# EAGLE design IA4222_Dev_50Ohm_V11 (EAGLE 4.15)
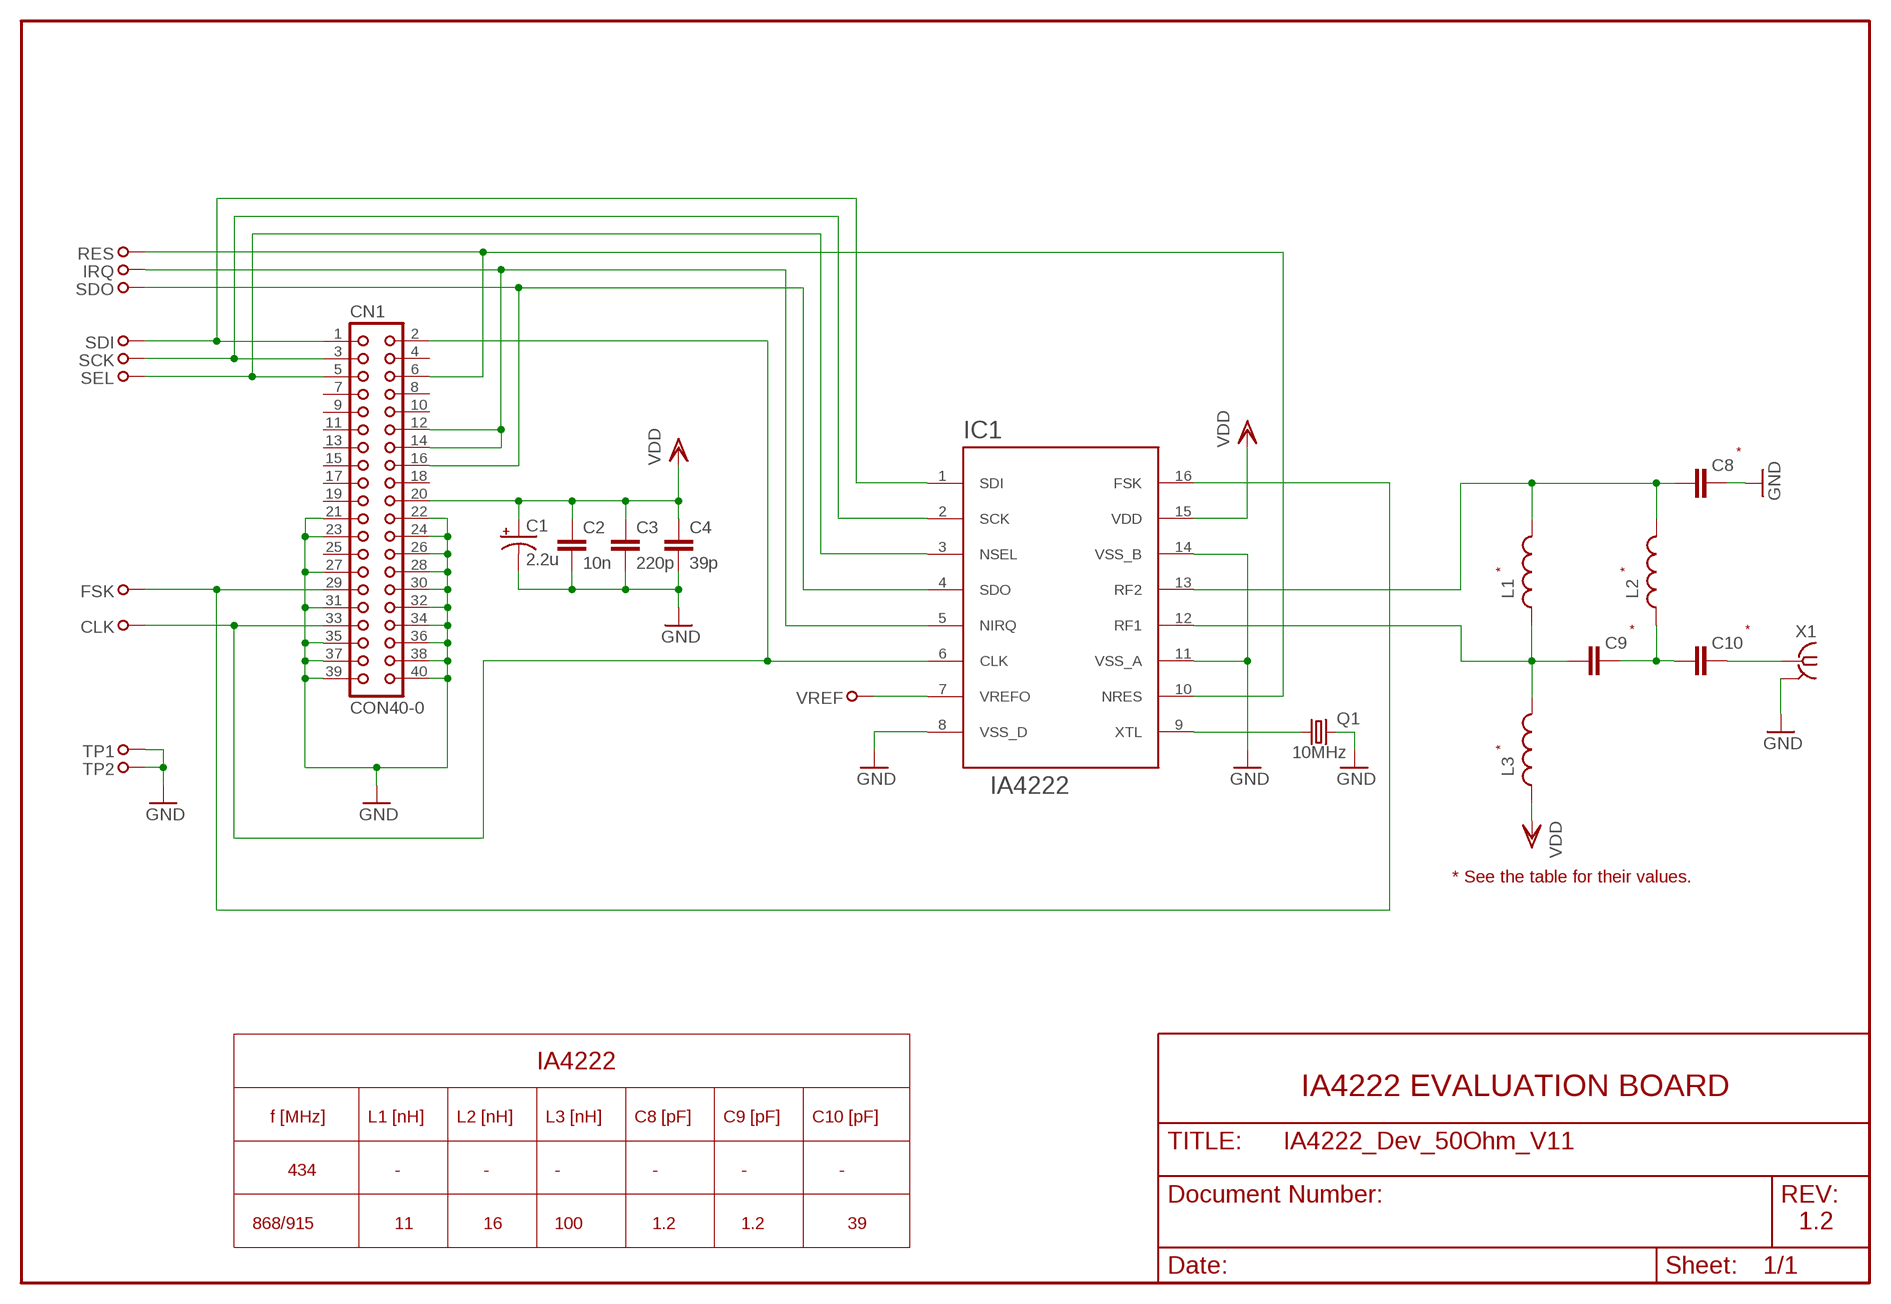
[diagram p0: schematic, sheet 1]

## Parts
C1  2.2u  CPOL-USA/3216-18R  [A/3216-18R]
C2  10n  C-EUC0603K  [C0603K]
C3  220p  C-EUC0603K  [C0603K]
C4  39p  C-EUC0603K  [C0603K]
C8  C-EUC0603K  [C0603K]
C9  C-EUC0603K  [C0603K]
C10  C-EUC0603K  [C0603K]
CLK  TESTPOINT39MIL  [TESTPOINT1,0]
CN1  CON40-0  [PANDUIT-057-040-0-INTEGRATION]
FSK  TESTPOINT39MIL  [TESTPOINT1,0]
IC1  IA4222  TESSIE  [TSSOP-16(NEW)]
IRQ  TESTPOINT39MIL  [TESTPOINT1,0]
L1  INDUCTCOILCRAFT-0603  [L1608]
L2  INDUCTCOILCRAFT-0603  [L1608]
L3  INDUCTCOILCRAFT-0603  [L1608]
Q1  10MHz  CRYTALSM49  [SM49]
RES  TESTPOINT39MIL  [TESTPOINT1,0]
SCK  TESTPOINT39MIL  [TESTPOINT1,0]
SDI  TESTPOINT39MIL  [TESTPOINT1,0]
SDO  TESTPOINT39MIL  [TESTPOINT1,0]
SEL  TESTPOINT39MIL  [TESTPOINT1,0]
TP1  TESTPOINT39MIL  [TESTPOINT1,0]
TP2  TESTPOINT39MIL  [TESTPOINT1,0]
VREF  TESTPOINT39MIL  [TESTPOINT1,0]
X1  BU-SMA-H  [BU-SMA-H]

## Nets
GND: C1.- C2.2 C3.2 C4.2 C8.2 CN1.21 CN1.22 CN1.23 CN1.24 CN1.26 CN1.27 CN1.28 CN1.30 CN1.31 CN1.32 CN1.34 CN1.35 CN1.36 CN1.37 CN1.38 CN1.39 CN1.40 IC1.8(VSS_D) IC1.11(VSS_A) IC1.14(VSS_B) Q1.2 TP1.1 TP2.1 X1.2(GND)
N$1: CN1.3 IC1.2(SCK) SCK.1
N$2: C8.1 IC1.13(RF2) L1.2 L2.2
N$3: CN1.5 IC1.3(NSEL) SEL.1
N$4: CLK.1 CN1.2 CN1.33 IC1.6(CLK)
N$5: IC1.7(VREFO) VREF.1
N$7: C9.1 IC1.12(RF1) L1.1 L3.2
N$8: IC1.9(XTL) Q1.1
N$9: CN1.12 CN1.14 IC1.5(NIRQ) IRQ.1
N$10: CN1.6 IC1.10(NRES) RES.1
N$11: C9.2 C10.1 L2.1
N$13: C10.2 X1.1
N$14: CN1.1 IC1.1(SDI) SDI.1
N$19: CN1.29 FSK.1 IC1.16(FSK)
TINA: CN1.16 IC1.4(SDO) SDO.1
VDD: C1.+ C2.1 C3.1 C4.1 CN1.20 IC1.15(VDD) L3.1
Unconnected: CN1.4 CN1.7 CN1.8 CN1.9 CN1.10 CN1.11 CN1.13 CN1.15 CN1.17 CN1.18 CN1.19 CN1.25

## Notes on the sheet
- *
- * | *
- * | *
- *
- * See the table for their values.
- IA4222
- IA4222 EVALUATION BOARD
- f [MHz] | L1 [nH] | L2 [nH] | L3 [nH] | C8 [pF] | C9 [pF] | C10 [pF]
- 434 | - | - | - | - | - | -
- 868/915 | 11 | 16 | 100 | 1.2 | 1.2 | 39 | 1.2

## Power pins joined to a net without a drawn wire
GND: X1.3(GND) X1.4(GND) X1.5(GND)

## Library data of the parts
C1 = rcl:CPOL-US: POLARIZED CAPACITOR, American symbol
C2-C4 C8-C10 = rcl:C-EU: CAPACITOR, European symbol
CLK FSK IRQ RES SCK SDI SDO SEL TP1 TP2 VREF = lve:TESTPOINT
CN1 = lve:CON40
IC1 = lve:TESSIE
L1-L3 = lve:INDUCT: SUMIDA
Q1 = crystal:CRYTAL: CRYSTAL
X1 = lve:BU-SMA-H: FEMALE SMA CONNECTOR Radiall distributor RS 193-9325

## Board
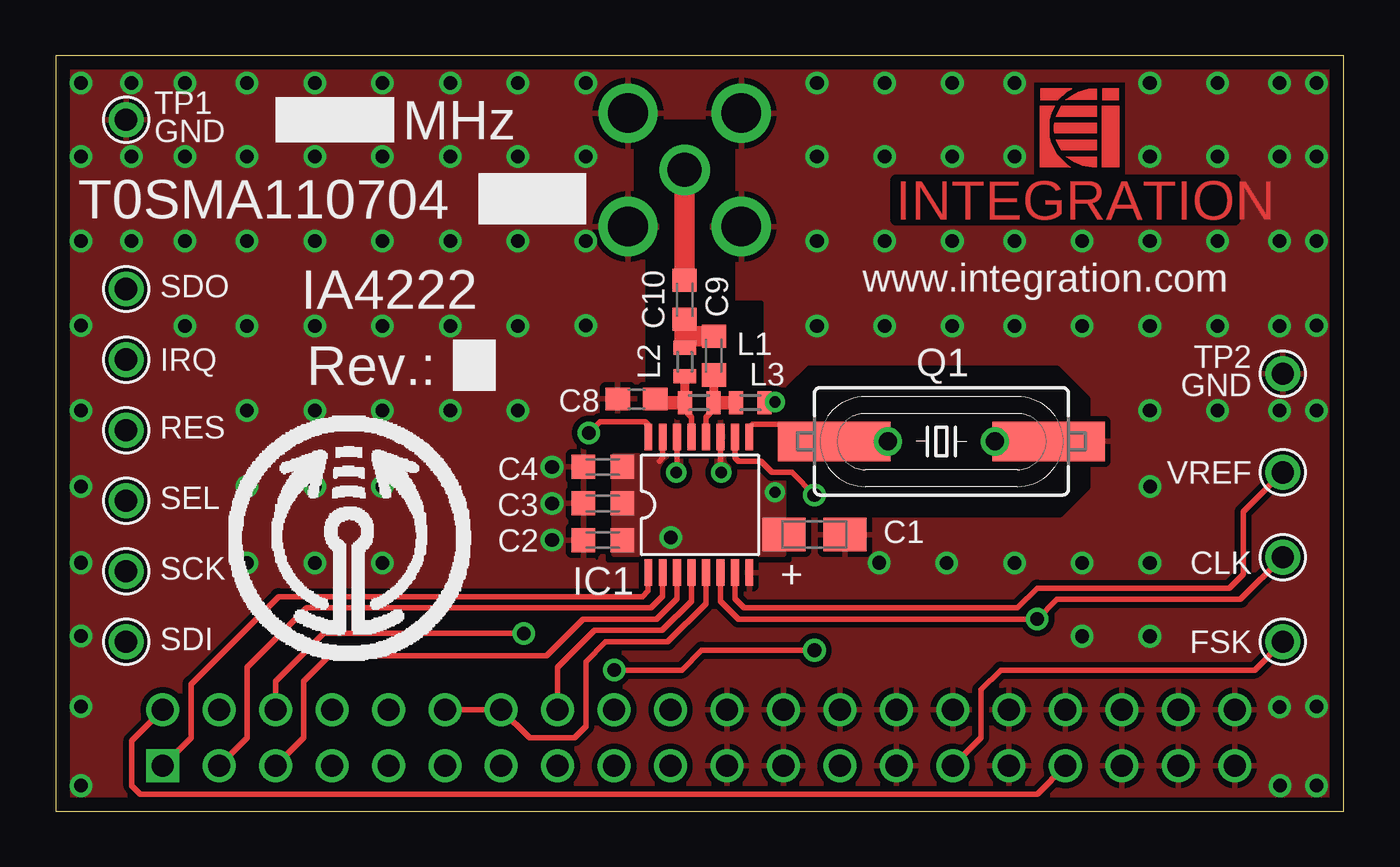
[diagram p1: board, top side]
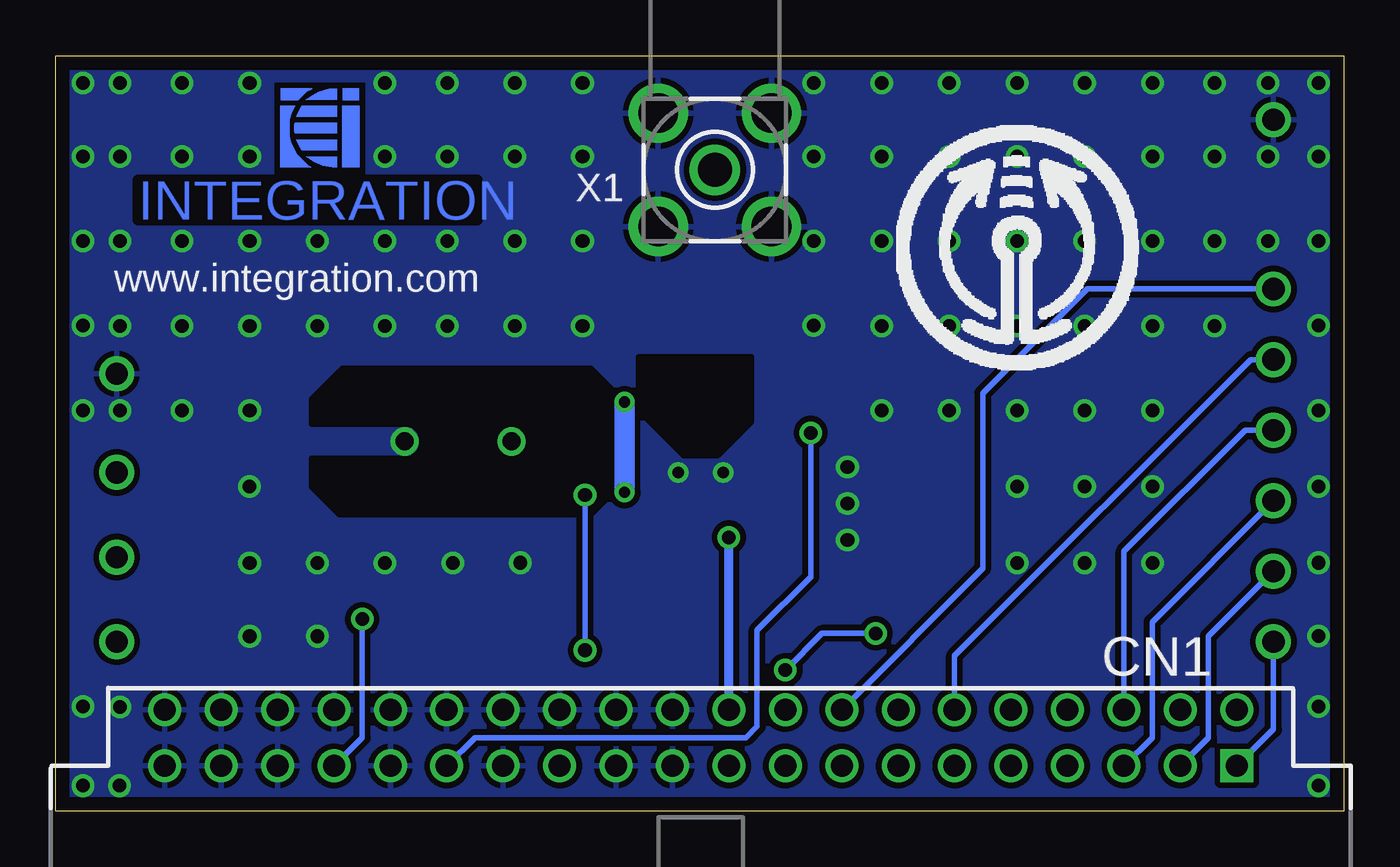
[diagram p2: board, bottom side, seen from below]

Size 58 x 34 mm. Coordinates in mm from the lower left corner, seen from the top.
Outline: 0,0 58,0 58,34 0,34 0,0
Copper layers (1*16): Top 0.035mm / dielectric 1.5mm / Bottom 0.035mm
Design rules "default_INTEGRATION": minimum track width 8mil, minimum drill 20mil, track to track 10mil, track to pad 10mil, pad to pad 10mil, via to via 10mil, smd to smd 0mil, copper to edge 25mil, drill to drill 8mil, minimum pad ring 8mil, minimum via ring 8mil, stop-mask expansion 4mil, vias tented up to drill 35mil, thermal gap 10mil
tRestrict: area 28.1,15.9 to 29.8,17.4; 23 lines
bRestrict: 17 lines

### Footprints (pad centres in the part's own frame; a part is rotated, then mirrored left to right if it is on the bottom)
A/3216-18R = smd 1.95 x 1.5: + 1.375,0; - -1.375,0
C0603K = smd 1.05 x 1.08: 1 -0.875,0; 2 0.875,0
C0603 = smd 1.1 x 1: 1 -0.85,0; 2 0.85,0
TESTPOINT1,0 = drill 1 pad 1.575 round: 1 0,0
PANDUIT-057-040-0-INTEGRATION = drill 0.991 square: 1 -24.13,-1.27 | drill 0.991 round: 2 -24.13,-3.81; 3 -21.59,-1.27; 4 -21.59,-3.81; 5 -19.05,-1.27; 6 -19.05,-3.81; 7 -16.51,-1.27; 8 -16.51,-3.81; 9 -13.97,-1.27; 10 -13.97,-3.81; 11 -11.43,-1.27; 12 -11.43,-3.81; 13 -8.89,-1.27; 14 -8.89,-3.81; 15 -6.35,-1.27; 16 -6.35,-3.81; 17 -3.81,-1.27; 18 -3.81,-3.81; 19 -1.27,-1.27; 20 -1.27,-3.81; 21 1.27,-1.27; 22 1.27,-3.81; 23 3.81,-1.27; 24 3.81,-3.81; 25 6.35,-1.27; 26 6.35,-3.81; 27 8.89,-1.27; 28 8.89,-3.81; 29 11.43,-1.27; 30 11.43,-3.81; 31 13.97,-1.27; 32 13.97,-3.81; 33 16.51,-1.27; 34 16.51,-3.81; 35 19.05,-1.27; 36 19.05,-3.81; 37 21.59,-1.27; 38 21.59,-3.81; 39 24.13,-1.27; 40 24.13,-3.81
TSSOP-16(NEW) = smd 1.2 x 0.35: 1 -3.107,2.275; 2 -3.107,1.625; 3 -3.107,0.975; 4 -3.107,0.325; 5 -3.107,-0.325; 6 -3.107,-0.975; 7 -3.107,-1.625; 8 -3.107,-2.275; 9 2.993,-2.275; 10 2.993,-1.625; 11 2.993,-0.975; 12 2.993,-0.325; 13 2.993,0.325; 14 2.993,0.975; 15 2.993,1.625; 16 2.993,2.275
L1608 = smd 0.64 x 1.02: 1 -0.64,0; 2 0.64,0
SM49 = smd 5.08 x 1.778: 1 -4.826,0; 2 4.826,0
BU-SMA-H = drill 1.524 pad 2.286 round: 1 0,0 | drill 1.778 pad 2.667 round: 2 -2.55,2.55; 3 2.55,2.55; 4 2.55,-2.55; 5 -2.55,-2.55

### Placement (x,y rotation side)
C1  34.16,12.45 180 top
C2  24.64,12.19 180 top
C3  24.64,13.84 180 top
C4  24.64,15.49 180 top
C8  [C0603]  26.16,18.55 180 top
C9  29.64,20.49 90 top
C10  28.32,23.01 90 top
CLK  55.24,11.43 0 top
CN1  28.96,0.76 180 bottom
FSK  55.24,7.62 0 top
IC1  28.96,13.84 90 top
IRQ  3.17,20.32 0 top
L1  28.98,18.37 180 top
L2  28.33,20.21 270 top
L3  31.28,18.37 180 top
Q1  39.88,16.64 0 top
RES  3.17,17.14 90 top
SCK  3.17,10.79 180 top
SDI  3.17,7.62 180 top
SDO  3.17,23.5 0 top
SEL  3.17,13.97 180 top
TP1  3.17,31.11 0 top
TP2  55.24,19.68 90 top
U$1  [LOGO-SMALL]  46.1,30.73 0 top
U$2  [LOGO-SMALL]  46.1,30.73 0 bottom
U$3  [TRANSMIT-ICON06]  14.73,25.65 0 bottom
U$4  [TRANSMIT-ICON06]  13.21,12.57 0 top
VREF  55.24,15.24 0 top
X1  28.32,28.85 90 bottom

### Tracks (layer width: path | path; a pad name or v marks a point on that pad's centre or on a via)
GND  (via drill 0.51 pad 0.91, 0.61 pad 1.02, 0.81 pad 1.27)
  Top 0.254: IC1.14 27.98,15.28 v27.94,15.24 | IC1.11 29.93,15.28 v29.97,15.24 | v42.29,16.64 Q1.2
  Top 0.406: Q1.2 45.85,16.64
  other vias: 8.62,18.03 14.72,18.03 17.77,18.03 20.81,18.03 8.62,11.17 11.67,11.17 14.72,11.17 8.62,14.6 11.67,14.6 14.72,14.6 55.1,18.03 52.31,18.03 49.26,18.03 40.12,11.17 43.17,11.17 46.21,11.17 49.26,11.17 55.1,4.69 1.14,18.03 1.14,14.61 1.14,11.18 1.14,4.7 1.14,1.14 56.77,1.14 56.77,4.7 56.77,18.03 22.35,12.19 55.12,1.14 23.88,25.65 23.88,21.84 55.1,25.65 52.31,25.65 49.26,25.65 46.21,25.65 43.17,25.65 56.77,25.65 55.1,21.84 52.31,21.84 49.26,21.84 46.21,21.84 43.17,21.84 56.77,21.84 3.42,25.65 5.83,25.65 8.62,25.65 11.67,25.65 14.72,25.65 17.77,25.65 20.81,25.65 1.14,25.65 5.83,21.84 8.62,21.84 14.72,21.84 17.77,21.84 20.81,21.84 1.14,21.84 49.26,7.87 46.21,7.87 1.14,7.87 23.88,29.46 3.42,29.46 5.83,29.46 8.62,29.46 14.72,29.46 17.77,29.46 20.81,29.46 1.14,29.46 55.1,29.46 52.31,29.46 49.26,29.46 43.17,29.46 56.77,29.46 40.37,25.65 37.32,25.65 34.28,25.65 40.37,21.84 37.32,21.84 34.28,21.84 40.37,29.46 37.32,29.46 34.28,29.46 23.88,32.77 55.1,32.76 52.31,32.76 49.26,32.76 43.17,32.76 56.77,32.77 3.42,32.76 5.83,32.76 8.62,32.76 14.72,32.76 17.77,32.76 20.81,32.76 1.14,32.77 40.37,32.76 37.32,32.76 34.28,32.76 11.67,18.03 11.67,21.84 22.35,13.84 22.35,15.49 37.08,11.18 49.28,14.61 11.67,29.46 11.67,32.76
  pour Top (rank 2): 0.13,0.13 57.78,0.13 57.78,33.78 0.13,33.78
  pour Bottom (rank 2): 0.13,0.13 57.78,0.13 57.78,33.78 0.13,33.78
N$1
  Top 0.254: IC1.2 27.33,9.68 26.8,9.14 11.3,9.14 8.64,6.48 8.64,3.3 CN1.3
  Bottom 0.254: SCK.1 6.1,7.87 6.1,3.3 CN1.3
N$2
  Top 0.254: L1.2 28.34,18.03 28.45,17.91 28.63,17.72 IC1.13
  Top 0.406: L1.2 28.34,19.66 L2.2
  Top 0.61: C8.1 27.1,18.55 27.28,18.37 L1.2
N$3
  Top 0.254: IC1.3 27.98,9.57 27.05,8.64 23.75,8.64 22.1,6.99 12.32,6.99 11.18,5.84 11.18,3.3 CN1.5
  Bottom 0.254: SEL.1 8.64,8.51 8.64,3.3 CN1.5
N$4  (via drill 0.61 pad 1.02)
  Top 0.254: CN1.33 44.2,0.76 3.81,0.76 3.43,1.14 3.43,3.17 CN1.2 | IC1.6 29.93,9.44 30.73,8.64 v44.2,8.64 45.09,9.53 53.34,9.53 CLK.1
  Bottom 0.254: CN1.33 44.2,3.3 v44.2,8.64
N$5
  Top 0.254: VREF.1 53.47,13.46 53.47,10.67 52.83,10.03 44.2,10.03 43.31,9.14 30.99,9.14 30.58,9.55 IC1.7
N$7
  Top 0.203: 29.46,17.91 29.62,18.03 L1.1
  Top 0.254: IC1.12 29.28,17.72 29.46,17.91
  Top 0.406: 29.69,18.37 29.66,18.34 L1.1 29.62,18.35 | 29.62,18.35 29.61,18.34 | C9.1 29.64,18.38 29.62,18.35
  Top 0.61: 29.69,18.37 L3.2
N$8  (via drill 0.81 pad 1.27)
  Top 0.254: IC1.9 31.23,17.26 31.37,17.4 34.29,17.4 Q1.1 v37.47,16.64
N$9
  Top 0.254: CN1.12 CN1.14 21.34,3.3 23.37,3.3 23.88,3.81 23.88,6.73 24.77,7.62 27.56,7.62 29.28,9.34 IC1.5
  Bottom 0.254: IRQ.1 4.19,20.32 17.53,6.99 CN1.12
N$10  (via drill 0.61 pad 1.02)
  Top 0.254: CN1.6 9.91,5.84 12.06,8 v21.08,8 | v25.15,6.35 28.19,6.35 29.08,7.24 v34.16,7.24 | IC1.10 30.58,15.9 30.73,15.75 31.75,15.75 32.26,15.24 33.15,15.24 v34.16,14.22
  Bottom 0.254: v34.16,7.24 v34.16,14.22 | v21.08,8 23.5,8 v25.15,6.35 | RES.1 4.45,17.14 9.91,11.68 CN1.6
N$11
  Top 0.406: L2.1 28.32,21.18
  Top 0.92: C9.2 | C9.2 | 28.32,21.18 28.32,21.36 | 28.32,21.36 C9.2 | 28.32,21.36 C10.1
N$13
  Top 0.92: C10.2 X1.1
N$14
  Top 0.254: CN1.1 6.1,3.3 6.1,5.71 10.03,9.65 26.42,9.65 26.68,9.92 IC1.1
  Bottom 0.254: SDI.1 3.17,3.68 CN1.1
N$19  (via drill 0.61 pad 1.02)
  Top 0.254: IC1.16 26.68,17.39 26.54,17.53 24.51,17.53 v24,17.02 | FSK.1 53.98,6.35 42.55,6.35 41.66,5.46 41.66,3.3 CN1.29
  Bottom 0.254: CN1.29 39.12,3.3 26.92,3.3 26.42,3.81 26.42,8.13 24,10.54 v24,17.02
TINA
  Top 0.254: CN1.16 22.61,6.48 24.26,8.13 27.3,8.13 28.63,9.45 IC1.4
  Bottom 0.254: SDO.1 11.56,23.5 16.26,18.8 16.26,10.92 CN1.16
VDD  (via drill 0.51 pad 0.91, 0.61 pad 1.02)
  Top 0.254: IC1.15 27.33,15.9 27.18,15.75
  Top 0.61: L3.1 32.34,18.37 v32.38,18.41
  Bottom 0.406: CN1.20 v27.69,12.32
  Bottom 0.914: v32.38,14.35 v32.38,18.41
  pour Top (no thermals): 25.15,11.56 25.15,16 32.77,16 32.77,11.56

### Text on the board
Top: INTEGRATION
Bottom: INTEGRATION
tPlace: GND | MHz | T0SMA110704 | IA4222 | www.integration.com | GND | Rev.: | +
bPlace: www.integration.com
